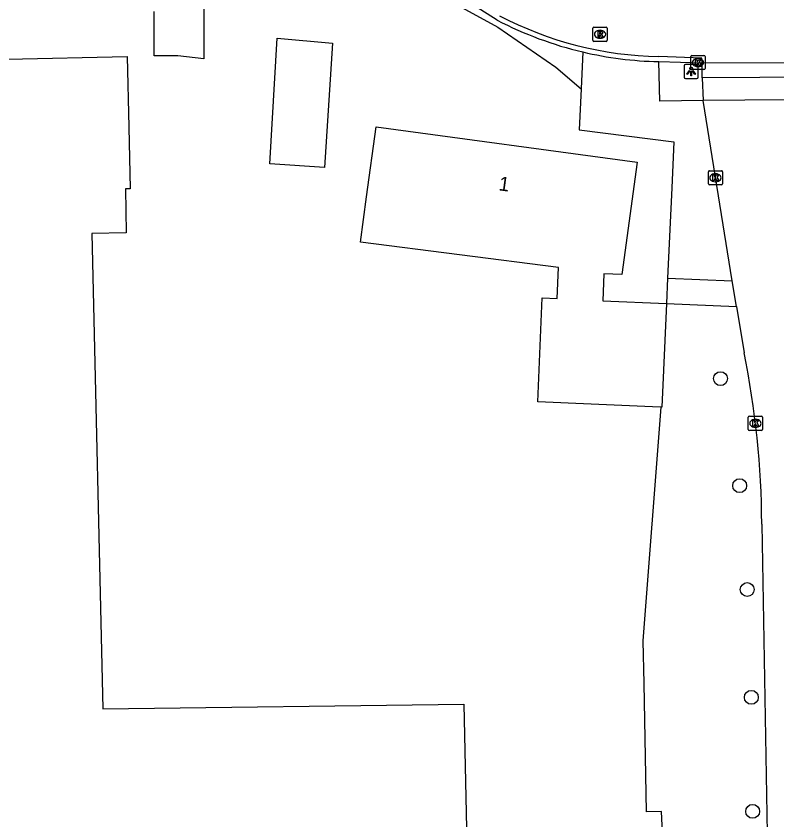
# Model space of a CAD drawing. Extents: x 157321 to 158827, y 386650 to 388532.
# Drawn here: x 157781.4 to 157835.1, y 387813.8 to 387870.6 of the extents above; entities that cross this region are included whole.
import ezdxf

# ---------------------------------------------------------------- set-up
doc = ezdxf.new("R2010")
doc.units = 0
for name, color, linetype in [('IMGEO_Boom', 7, 'Continuous'), ('IMGEO_Groenvoorziening', 7, 'Continuous'), ('IMGEO_Kolk', 7, 'Continuous'), ('IMGEO_Lichtpunt', 7, 'Continuous'), ('IMGEO_Pand', 7, 'Continuous'), ('IMGEO_Pand_nummerreeks', 7, 'Continuous'), ('IMGEO_Rijbaan_lokaal_open', 7, 'Continuous'), ('IMGEO_Rioolput', 7, 'Continuous'), ('IMGEO_Voetpad_open', 7, 'Continuous')]:
    doc.layers.add(name, color=color, linetype=linetype)

msp = doc.modelspace()

# ---------------------------------------------------------------- linework, layer by layer
at = {"layer": 'IMGEO_Boom'}
for centre in [(157831.122, 387844.996), (157832.474, 387837.439), (157833.009, 387830.104), (157833.297, 387822.496), (157833.389, 387814.448)]:
    msp.add_circle(centre, 0.489, dxfattribs=at)
at = {"layer": 'IMGEO_Groenvoorziening'}
for points in [[(157805.424, 387872.506), (157811.045, 387872.207), (157815.393, 387869.812), (157819.498, 387866.986), (157821.272, 387865.463)], [(157821.394, 387868.054), (157821.272, 387865.463)], [(157821.272, 387865.463), (157821.136, 387862.564), (157827.833, 387861.72), (157827.681, 387858.474), (157827.381, 387852.087)], [(157827.188, 387805.473), (157827.029, 387811.882), (157826.99, 387813.448), (157826.965, 387814.434), (157825.896, 387814.425), (157825.724, 387823.468), (157825.654, 387826.485), (157826.933, 387842.981)]]:
    msp.add_lwpolyline(points, dxfattribs=at)
at = {"layer": 'IMGEO_Kolk'}
for p, q in [((157829.027, 387866.881), (157829.027, 387867.733)), ((157829.102, 387867.807), (157829.954, 387867.807)), ((157829.515, 387867.587), (157829.54, 387867.587)), ((157830.028, 387867.733), (157830.028, 387866.881)), ((157829.538, 387867.027), (157829.513, 387867.027)), ((157829.954, 387866.807), (157829.102, 387866.807)), ((157830.262, 387858.748), (157830.262, 387859.6)), ((157830.337, 387859.674), (157831.189, 387859.674)), ((157831.263, 387859.6), (157831.263, 387858.748)), ((157830.75, 387859.454), (157830.775, 387859.454)), ((157831.189, 387858.674), (157830.337, 387858.674)), ((157830.773, 387858.894), (157830.748, 387858.894)), ((157833.085, 387841.412), (157833.085, 387842.264)), ((157833.16, 387842.338), (157834.012, 387842.338)), ((157833.573, 387842.118), (157833.598, 387842.118)), ((157834.086, 387842.264), (157834.086, 387841.412)), ((157833.596, 387841.558), (157833.571, 387841.558)), ((157834.012, 387841.338), (157833.16, 387841.338))]:
    msp.add_line(p, q, dxfattribs=at)
for points in [[(157829.027, 387866.881), (157829.027, 387867.733)], [(157829.102, 387867.807), (157829.954, 387867.807)], [(157830.028, 387867.733), (157830.028, 387866.881)], [(157829.348, 387867.507), (157829.471, 387867.507), (157829.471, 387867.356), (157829.601, 387867.507), (157829.765, 387867.507), (157829.619, 387867.356), (157829.772, 387867.107), (157829.62, 387867.107), (157829.535, 387867.271), (157829.471, 387867.204), (157829.471, 387867.107), (157829.348, 387867.107), (157829.348, 387867.507)], [(157829.954, 387866.807), (157829.102, 387866.807)], [(157830.262, 387858.748), (157830.262, 387859.6)], [(157830.337, 387859.674), (157831.189, 387859.674)], [(157831.263, 387859.6), (157831.263, 387858.748)], [(157830.583, 387859.374), (157830.706, 387859.374), (157830.706, 387859.223), (157830.836, 387859.374), (157831, 387859.374), (157830.854, 387859.223), (157831.007, 387858.974), (157830.855, 387858.974), (157830.77, 387859.138), (157830.706, 387859.071), (157830.706, 387858.974), (157830.583, 387858.974), (157830.583, 387859.374)], [(157831.189, 387858.674), (157830.337, 387858.674)], [(157833.085, 387841.412), (157833.085, 387842.264)], [(157833.16, 387842.338), (157834.012, 387842.338)], [(157833.406, 387842.038), (157833.529, 387842.038), (157833.529, 387841.887), (157833.659, 387842.038), (157833.823, 387842.038), (157833.677, 387841.887), (157833.83, 387841.638), (157833.678, 387841.638), (157833.593, 387841.802), (157833.529, 387841.735), (157833.529, 387841.638), (157833.406, 387841.638), (157833.406, 387842.038)], [(157834.086, 387842.264), (157834.086, 387841.412)], [(157834.012, 387841.338), (157833.16, 387841.338)]]:
    msp.add_lwpolyline(points, dxfattribs=at)
for centre, start, end in [((157829.104, 387867.731), 91.552, 178.448), ((157829.104, 387867.731), 91.552, 178.448), ((157829.952, 387867.731), 1.552, 88.448), ((157829.952, 387867.731), 1.552, 88.448), ((157829.104, 387866.883), 181.552, 268.448), ((157829.104, 387866.883), 181.552, 268.448), ((157829.952, 387866.883), 271.552, 358.448), ((157829.952, 387866.883), 271.552, 358.448), ((157830.339, 387859.598), 91.552, 178.448), ((157830.339, 387859.598), 91.552, 178.448), ((157831.187, 387859.598), 1.552, 88.448), ((157831.187, 387859.598), 1.552, 88.448), ((157830.339, 387858.75), 181.552, 268.448), ((157830.339, 387858.75), 181.552, 268.448), ((157831.187, 387858.75), 271.552, 358.448), ((157831.187, 387858.75), 271.552, 358.448), ((157833.162, 387842.262), 91.552, 178.448), ((157833.162, 387842.262), 91.552, 178.448), ((157834.01, 387842.262), 1.552, 88.448), ((157834.01, 387842.262), 1.552, 88.448), ((157833.162, 387841.414), 181.552, 268.448), ((157833.162, 387841.414), 181.552, 268.448), ((157834.01, 387841.414), 271.552, 358.448), ((157834.01, 387841.414), 271.552, 358.448)]:
    msp.add_arc(centre, 0.0765, start, end, dxfattribs=at)
for centre, major_axis, ratio, start_param, end_param in [((157829.514, 387867.307), (-0.387, 0.002), 0.722429, 4.712389, 7.853982), ((157829.539, 387867.307), (-0.39, 0.002), 0.717154, 1.570796, 4.712389), ((157830.749, 387859.174), (-0.387, 0.002), 0.722429, 4.712389, 7.853982), ((157830.774, 387859.174), (-0.39, 0.002), 0.717154, 1.570796, 4.712389), ((157833.572, 387841.838), (-0.387, 0.002), 0.722429, 4.712389, 7.853982), ((157833.597, 387841.838), (-0.39, 0.002), 0.717154, 1.570796, 4.712389)]:
    msp.add_ellipse(centre, major_axis=major_axis, ratio=ratio, start_param=start_param, end_param=end_param, dxfattribs=at)
at = {"layer": 'IMGEO_Lichtpunt'}
for p, q in [((157828.546, 387867.085), (157828.546, 387866.278)), ((157828.546, 387867.085), (157828.546, 387866.278)), ((157829.448, 387867.18), (157828.64, 387867.18)), ((157829.448, 387867.18), (157828.64, 387867.18)), ((157829.542, 387866.278), (157829.542, 387867.085)), ((157829.542, 387866.278), (157829.542, 387867.085)), ((157828.64, 387866.184), (157829.448, 387866.184)), ((157828.64, 387866.184), (157829.448, 387866.184))]:
    msp.add_line(p, q, dxfattribs=at)
for points in [[(157828.92, 387866.749), (157828.959, 387866.721), (157828.771, 387866.459), (157828.733, 387866.486), (157828.92, 387866.749)], [(157829.022, 387866.701), (157829.069, 387866.701), (157829.069, 387866.379), (157829.022, 387866.379), (157829.022, 387866.701)], [(157829.132, 387866.721), (157829.17, 387866.748), (157829.357, 387866.486), (157829.318, 387866.458), (157829.132, 387866.721)]]:
    msp.add_lwpolyline(points, dxfattribs=at)
msp.add_circle((157829.045, 387866.883), 0.0994, dxfattribs=at)
for centre, start, end in [((157828.64, 387867.085), 90, 180), ((157828.64, 387867.085), 90, 180), ((157829.448, 387867.085), 0, 90), ((157829.448, 387867.085), 0, 90), ((157828.64, 387866.278), 180, 270), ((157828.64, 387866.278), 180, 270), ((157829.448, 387866.278), 270, 0), ((157829.448, 387866.278), 270, 360)]:
    msp.add_arc(centre, 0.0946, start, end, dxfattribs=at)
at = {"layer": 'IMGEO_Pand'}
for points in [[(157799.304, 387860.147), (157799.822, 387869.034), (157803.726, 387868.686), (157803.163, 387859.895), (157799.304, 387860.147)], [(157780.768, 387867.557), (157789.226, 387867.736), (157789.331, 387862.738), (157789.423, 387858.398), (157789.093, 387858.391), (157789.159, 387855.292), (157786.725, 387855.24), (157787.494, 387821.679)], [(157826.933, 387842.981), (157826.318, 387843.008), (157821.99, 387843.193), (157818.222, 387843.354), (157818.536, 387850.705), (157819.593, 387850.659), (157819.686, 387852.841), (157805.688, 387854.63), (157806.123, 387857.824), (157806.798, 387862.778), (157825.243, 387860.264), (157824.162, 387852.343), (157822.889, 387852.397), (157822.808, 387850.481), (157827.297, 387850.289)], [(157827.297, 387850.289), (157826.985, 387842.979), (157826.933, 387842.981)], [(157787.494, 387821.679), (157813.002, 387822.024), (157813.23, 387811.054), (157801.16, 387810.785), (157801.321, 387803.798), (157793.154, 387803.611), (157793.146, 387803.961), (157790.557, 387803.902), (157790.564, 387803.562), (157768.094, 387803.067)]]:
    msp.add_lwpolyline(points, dxfattribs=at)
at = {"layer": 'IMGEO_Rijbaan_lokaal_open'}
for points in [[(157815.352, 387870.305), (157812.407, 387872.192)], [(157829.817, 387867.277), (157829.802, 387867.616), (157826.763, 387867.724)], [(157826.756, 387867.374), (157829.817, 387867.277)], [(157829.817, 387867.277), (157837.963, 387867.316)], [(157835.773, 387864.664), (157829.885, 387864.638)], [(157831.955, 387851.91), (157829.885, 387864.638)], [(157832.25, 387850.097), (157831.955, 387851.91)], [(157832.25, 387850.097), (157832.783, 387846.822)], [(157834.035, 387834.73), (157834.417, 387812.882), (157834.444, 387811.356), (157834.547, 387805.493)]]:
    msp.add_lwpolyline(points, dxfattribs=at)
for centre, radius, start, end in [((157827.287, 387893.095), 25.376, 242.3624, 268.8159), ((157827.363, 387893.311), 25.953, 242.431, 256.7024), ((157827.298, 387893.129), 25.761, 256.7507, 268.7941), ((157771.38, 387834.354), 62.657, 0.34429, 11.47834)]:
    msp.add_arc(centre, radius, start, end, dxfattribs=at)
at = {"layer": 'IMGEO_Rioolput'}
for p, q in [((157822.186, 387869.802), (157823.038, 387869.802)), ((157822.111, 387868.876), (157822.111, 387869.728)), ((157822.599, 387869.582), (157822.624, 387869.582)), ((157823.112, 387869.728), (157823.112, 387868.876)), ((157823.038, 387868.802), (157822.186, 387868.802)), ((157822.622, 387869.022), (157822.597, 387869.022))]:
    msp.add_line(p, q, dxfattribs=at)
for points in [[(157822.186, 387869.802), (157823.038, 387869.802)], [(157822.111, 387868.876), (157822.111, 387869.728)], [(157822.7, 387869.5), (157822.448, 387869.502), (157822.448, 387869.102)], [(157822.448, 387869.102), (157822.572, 387869.102), (157822.572, 387869.264), (157822.583, 387869.264)], [(157822.626, 387869.421), (157822.572, 387869.421), (157822.572, 387869.34)], [(157822.572, 387869.34), (157822.624, 387869.34)], [(157822.63, 387869.235), (157822.701, 387869.102), (157822.841, 387869.102), (157822.776, 387869.228)], [(157823.112, 387869.728), (157823.112, 387868.876)], [(157823.038, 387868.802), (157822.186, 387868.802)]]:
    msp.add_lwpolyline(points, dxfattribs=at)
for centre, radius, start, end in [((157822.188, 387869.726), 0.0765, 91.552, 178.448), ((157822.188, 387869.726), 0.0765, 91.552, 178.448), ((157823.036, 387869.726), 0.0765, 1.552, 88.448), ((157823.036, 387869.726), 0.0765, 1.552, 88.448), ((157822.582, 387869.211), 0.0533, 26.0293, 88.6989), ((157822.608, 387869.529), 0.19, 274.7715, 282.9687), ((157822.632, 387869.325), 0.0964, 77.0061, 93.1865), ((157822.646, 387869.382), 0.0378, 276.6634, 79.6772), ((157822.699, 387869.39), 0.109, 350.3612, 89.416), ((157822.697, 387869.39), 0.112, 277.5842, 350.9817), ((157822.681, 387869.175), 0.108, 29.5134, 73.7905), ((157822.188, 387868.878), 0.0765, 181.552, 268.448), ((157822.188, 387868.878), 0.0765, 181.552, 268.448), ((157823.036, 387868.878), 0.0765, 271.552, 358.448), ((157823.036, 387868.878), 0.0765, 271.552, 358.448)]:
    msp.add_arc(centre, radius, start, end, dxfattribs=at)
for centre, major_axis, ratio, start_param, end_param in [((157822.598, 387869.302), (-0.387, 0.002), 0.722429, 4.712389, 7.853982), ((157822.623, 387869.302), (-0.39, 0.002), 0.717154, 1.570796, 4.712389)]:
    msp.add_ellipse(centre, major_axis=major_axis, ratio=ratio, start_param=start_param, end_param=end_param, dxfattribs=at)
at = {"layer": 'IMGEO_Voetpad_open'}
for points in [[(157794.628, 387873.079), (157794.628, 387867.566), (157792.797, 387867.776), (157791.134, 387867.776), (157791.134, 387870.919)], [(157829.885, 387864.638), (157826.837, 387864.58), (157826.756, 387867.374)], [(157829.822, 387866.237), (157829.817, 387867.277)], [(157837.963, 387867.316), (157837.968, 387866.276), (157829.822, 387866.237)], [(157829.822, 387866.237), (157829.885, 387864.638)], [(157827.381, 387852.087), (157827.297, 387850.289)], [(157827.381, 387852.087), (157831.955, 387851.91)], [(157827.297, 387850.289), (157832.25, 387850.097)]]:
    msp.add_lwpolyline(points, dxfattribs=at)

# ---------------------------------------------------------------- texts
at = {"layer": 'IMGEO_Pand_nummerreeks'}
msp.add_text('1', height=1, rotation=352.2364, dxfattribs=at).set_placement((157815.418, 387858.294))

doc.saveas('drawing.dxf')
